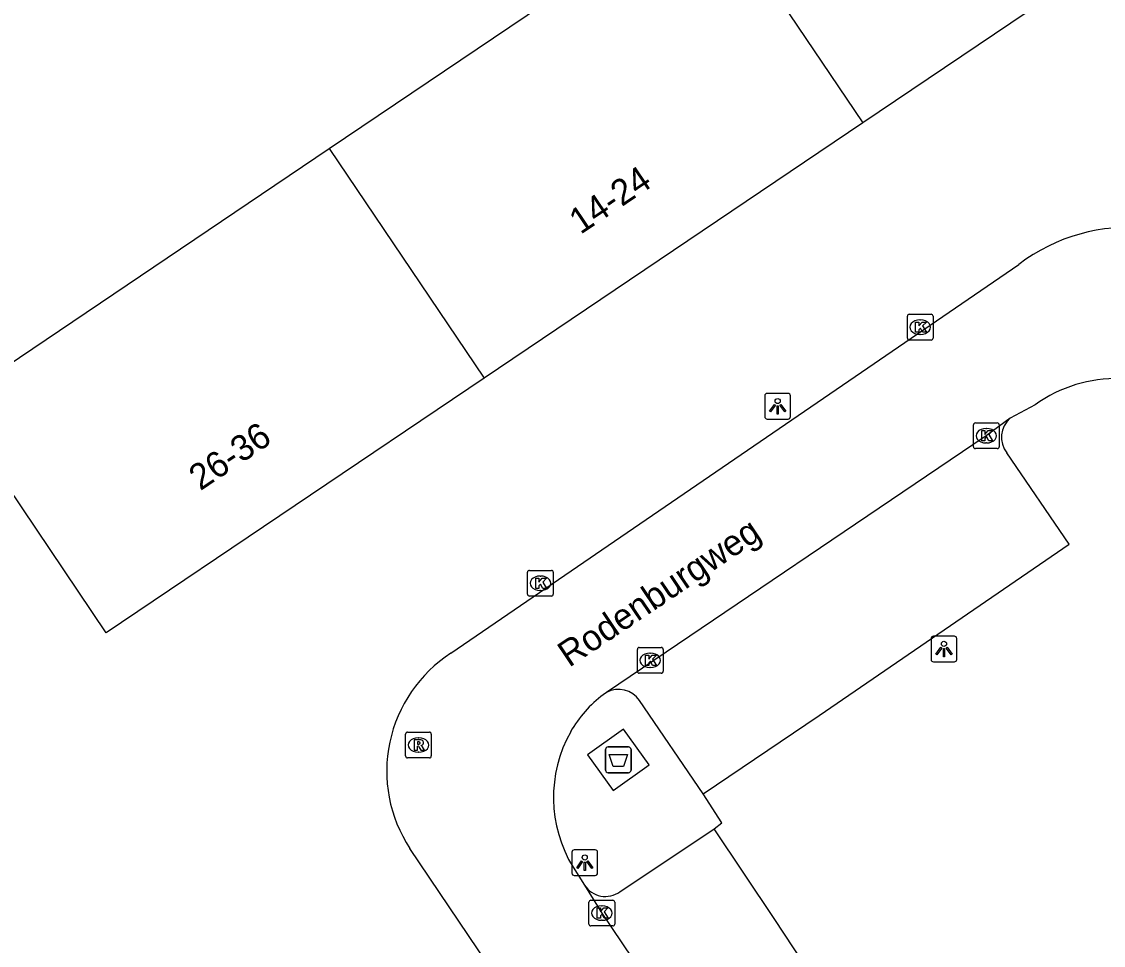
# Model space of a CAD drawing. Extents: x 157466 to 158888, y 383063 to 384677.
# Drawn here: x 158011.77 to 158053.8, y 383756.98 to 383792.86 of the extents above; entities that cross this region are included whole.
import ezdxf

# ---------------------------------------------------------------- set-up
doc = ezdxf.new("R2010")
doc.units = 0
for name, color, linetype in [('IMGEO_Afval_apart_plaats', 7, 'Continuous'), ('IMGEO_Kolk', 7, 'Continuous'), ('IMGEO_Lichtpunt', 7, 'Continuous'), ('IMGEO_Openbare_ruimte_label', 7, 'Continuous'), ('IMGEO_Pand', 7, 'Continuous'), ('IMGEO_Pand_nummerreeks', 7, 'Continuous'), ('IMGEO_Parkeervlak_open', 7, 'Continuous'), ('IMGEO_Rijbaan_lokaal_open', 7, 'Continuous'), ('IMGEO_Rioolput', 7, 'Continuous'), ('IMGEO_Voetpad_gesloten', 7, 'Continuous'), ('IMGEO_Voetpad_open', 7, 'Continuous')]:
    doc.layers.add(name, color=color, linetype=linetype)

msp = doc.modelspace()

# ---------------------------------------------------------------- linework, layer by layer
at = {"layer": 'IMGEO_Afval_apart_plaats'}
for p, q in [((158034.456, 383763.782), (158034.456, 383764.582)), ((158034.456, 383764.582), (158034.456, 383763.782)), ((158034.556, 383764.682), (158035.346, 383764.682)), ((158035.346, 383764.682), (158034.556, 383764.682)), ((158035.446, 383764.582), (158035.446, 383763.782)), ((158035.446, 383763.782), (158035.446, 383764.582)), ((158035.346, 383763.682), (158034.556, 383763.682)), ((158034.556, 383763.682), (158035.346, 383763.682))]:
    msp.add_line(p, q, dxfattribs=at)
msp.add_lwpolyline([(158034.599, 383764.396), (158035.303, 383764.396), (158035.154, 383763.926), (158034.748, 383763.926), (158034.599, 383764.396)], dxfattribs=at)
for centre, start, end in [((158034.556, 383764.582), 90, 180), ((158034.556, 383764.582), 90, 180), ((158035.346, 383764.582), 0, 90), ((158035.346, 383764.582), 360, 90), ((158034.556, 383763.782), 180, 270), ((158034.556, 383763.782), 180, 270), ((158035.346, 383763.782), 270, 0), ((158035.346, 383763.782), 270, 0)]:
    msp.add_arc(centre, 0.1, start, end, dxfattribs=at)
at = {"layer": 'IMGEO_Kolk'}
for p, q in [((158046.182, 383780.564), (158046.182, 383781.416)), ((158046.257, 383781.49), (158047.109, 383781.49)), ((158046.67, 383781.27), (158046.695, 383781.27)), ((158047.183, 383781.416), (158047.183, 383780.564)), ((158047.109, 383780.49), (158046.257, 383780.49)), ((158046.693, 383780.71), (158046.668, 383780.71)), ((158048.748, 383776.347), (158048.748, 383777.199)), ((158048.823, 383777.273), (158049.675, 383777.273)), ((158049.236, 383777.053), (158049.261, 383777.053)), ((158049.749, 383777.199), (158049.749, 383776.347)), ((158049.675, 383776.273), (158048.823, 383776.273)), ((158049.259, 383776.493), (158049.234, 383776.493)), ((158031.499, 383771.542), (158032.351, 383771.542)), ((158031.424, 383770.616), (158031.424, 383771.468)), ((158031.912, 383771.322), (158031.937, 383771.322)), ((158032.425, 383771.468), (158032.425, 383770.616)), ((158031.935, 383770.762), (158031.91, 383770.762)), ((158032.351, 383770.542), (158031.499, 383770.542)), ((158035.694, 383767.622), (158035.694, 383768.474)), ((158035.769, 383768.548), (158036.621, 383768.548)), ((158036.182, 383768.328), (158036.207, 383768.328)), ((158036.695, 383768.474), (158036.695, 383767.622)), ((158036.205, 383767.768), (158036.18, 383767.768)), ((158036.621, 383767.548), (158035.769, 383767.548)), ((158033.812, 383757.804), (158033.812, 383758.656)), ((158033.887, 383758.73), (158034.739, 383758.73)), ((158034.3, 383758.51), (158034.325, 383758.51)), ((158034.813, 383758.656), (158034.813, 383757.804)), ((158034.739, 383757.73), (158033.887, 383757.73)), ((158034.323, 383757.95), (158034.298, 383757.95))]:
    msp.add_line(p, q, dxfattribs=at)
for points in [[(158046.182, 383780.564), (158046.182, 383781.416)], [(158046.257, 383781.49), (158047.109, 383781.49)], [(158046.503, 383781.19), (158046.626, 383781.19), (158046.626, 383781.039), (158046.756, 383781.19), (158046.92, 383781.19), (158046.774, 383781.039), (158046.927, 383780.79), (158046.775, 383780.79), (158046.69, 383780.954), (158046.626, 383780.887), (158046.626, 383780.79), (158046.503, 383780.79), (158046.503, 383781.19)], [(158047.183, 383781.416), (158047.183, 383780.564)], [(158047.109, 383780.49), (158046.257, 383780.49)], [(158048.748, 383776.347), (158048.748, 383777.199)], [(158048.823, 383777.273), (158049.675, 383777.273)], [(158049.069, 383776.973), (158049.192, 383776.973), (158049.192, 383776.822), (158049.322, 383776.973), (158049.486, 383776.973), (158049.34, 383776.822), (158049.493, 383776.573), (158049.341, 383776.573), (158049.256, 383776.737), (158049.192, 383776.67), (158049.192, 383776.573), (158049.069, 383776.573), (158049.069, 383776.973)], [(158049.749, 383777.199), (158049.749, 383776.347)], [(158049.675, 383776.273), (158048.823, 383776.273)], [(158031.499, 383771.542), (158032.351, 383771.542)], [(158031.424, 383770.616), (158031.424, 383771.468)], [(158031.745, 383771.242), (158031.868, 383771.242), (158031.868, 383771.091), (158031.998, 383771.242), (158032.162, 383771.242), (158032.016, 383771.091), (158032.169, 383770.842), (158032.017, 383770.842), (158031.932, 383771.006), (158031.868, 383770.939), (158031.868, 383770.842), (158031.745, 383770.842), (158031.745, 383771.242)], [(158032.425, 383771.468), (158032.425, 383770.616)], [(158032.351, 383770.542), (158031.499, 383770.542)], [(158035.694, 383767.622), (158035.694, 383768.474)], [(158035.769, 383768.548), (158036.621, 383768.548)], [(158036.015, 383768.248), (158036.138, 383768.248), (158036.138, 383768.097), (158036.268, 383768.248), (158036.432, 383768.248), (158036.286, 383768.097), (158036.439, 383767.848), (158036.287, 383767.848), (158036.202, 383768.012), (158036.138, 383767.945), (158036.138, 383767.848), (158036.015, 383767.848), (158036.015, 383768.248)], [(158036.695, 383768.474), (158036.695, 383767.622)], [(158036.621, 383767.548), (158035.769, 383767.548)], [(158033.812, 383757.804), (158033.812, 383758.656)], [(158033.887, 383758.73), (158034.739, 383758.73)], [(158034.813, 383758.656), (158034.813, 383757.804)], [(158034.133, 383758.43), (158034.256, 383758.43), (158034.256, 383758.279), (158034.386, 383758.43), (158034.55, 383758.43), (158034.404, 383758.279), (158034.557, 383758.03), (158034.405, 383758.03), (158034.32, 383758.194), (158034.256, 383758.127), (158034.256, 383758.03), (158034.133, 383758.03), (158034.133, 383758.43)], [(158034.739, 383757.73), (158033.887, 383757.73)]]:
    msp.add_lwpolyline(points, dxfattribs=at)
for centre, start, end in [((158046.259, 383781.414), 91.552, 178.448), ((158046.259, 383781.414), 91.552, 178.448), ((158047.107, 383781.414), 1.552, 88.448), ((158047.107, 383781.414), 1.552, 88.448), ((158046.259, 383780.566), 181.552, 268.448), ((158046.259, 383780.566), 181.552, 268.448), ((158047.107, 383780.566), 271.552, 358.448), ((158047.107, 383780.566), 271.552, 358.448), ((158048.825, 383777.197), 91.552, 178.448), ((158048.825, 383777.197), 91.552, 178.448), ((158049.673, 383777.197), 1.552, 88.448), ((158049.673, 383777.197), 1.552, 88.448), ((158048.825, 383776.349), 181.552, 268.448), ((158048.825, 383776.349), 181.552, 268.448), ((158049.673, 383776.349), 271.552, 358.448), ((158049.673, 383776.349), 271.552, 358.448), ((158031.501, 383771.466), 91.552, 178.448), ((158031.501, 383771.466), 91.552, 178.448), ((158032.349, 383771.466), 1.552, 88.448), ((158032.349, 383771.466), 1.552, 88.448), ((158031.501, 383770.618), 181.552, 268.448), ((158031.501, 383770.618), 181.552, 268.448), ((158032.349, 383770.618), 271.552, 358.448), ((158032.349, 383770.618), 271.552, 358.448), ((158035.771, 383768.472), 91.552, 178.448), ((158035.771, 383768.472), 91.552, 178.448), ((158036.619, 383768.472), 1.552, 88.448), ((158036.619, 383768.472), 1.552, 88.448), ((158035.771, 383767.624), 181.552, 268.448), ((158035.771, 383767.624), 181.552, 268.448), ((158036.619, 383767.624), 271.552, 358.448), ((158036.619, 383767.624), 271.552, 358.448), ((158033.889, 383758.654), 91.552, 178.448), ((158033.889, 383758.654), 91.552, 178.448), ((158034.737, 383758.654), 1.552, 88.448), ((158034.737, 383758.654), 1.552, 88.448), ((158033.889, 383757.806), 181.552, 268.448), ((158033.889, 383757.806), 181.552, 268.448), ((158034.737, 383757.806), 271.552, 358.448), ((158034.737, 383757.806), 271.552, 358.448)]:
    msp.add_arc(centre, 0.0765, start, end, dxfattribs=at)
for centre, major_axis, ratio, start_param, end_param in [((158046.669, 383780.99), (-0.387, 0.002), 0.722429, 4.712389, 7.853982), ((158046.694, 383780.99), (-0.39, 0.002), 0.717154, 1.570796, 4.712389), ((158049.235, 383776.773), (-0.387, 0.002), 0.722429, 4.712389, 7.853982), ((158049.26, 383776.773), (-0.39, 0.002), 0.717154, 1.570796, 4.712389), ((158031.911, 383771.042), (-0.387, 0.002), 0.722429, 4.712389, 7.853982), ((158031.936, 383771.042), (-0.39, 0.002), 0.717154, 1.570796, 4.712389), ((158036.181, 383768.048), (-0.387, 0.002), 0.722429, 4.712389, 7.853982), ((158036.206, 383768.048), (-0.39, 0.002), 0.717154, 1.570796, 4.712389), ((158034.299, 383758.23), (-0.387, 0.002), 0.722429, 4.712389, 7.853982), ((158034.324, 383758.23), (-0.39, 0.002), 0.717154, 1.570796, 4.712389)]:
    msp.add_ellipse(centre, major_axis=major_axis, ratio=ratio, start_param=start_param, end_param=end_param, dxfattribs=at)
at = {"layer": 'IMGEO_Lichtpunt'}
for p, q in [((158040.644, 383778.323), (158040.644, 383777.516)), ((158040.644, 383778.323), (158040.644, 383777.516)), ((158041.546, 383778.418), (158040.738, 383778.418)), ((158041.546, 383778.418), (158040.738, 383778.418)), ((158041.64, 383777.516), (158041.64, 383778.323)), ((158041.64, 383777.516), (158041.64, 383778.323)), ((158040.738, 383777.422), (158041.546, 383777.422)), ((158040.738, 383777.422), (158041.546, 383777.422)), ((158048.007, 383768.986), (158047.199, 383768.986)), ((158048.007, 383768.986), (158047.199, 383768.986)), ((158047.105, 383768.891), (158047.105, 383768.084)), ((158047.105, 383768.891), (158047.105, 383768.084)), ((158048.101, 383768.084), (158048.101, 383768.891)), ((158048.101, 383768.084), (158048.101, 383768.891)), ((158047.199, 383767.99), (158048.007, 383767.99)), ((158047.199, 383767.99), (158048.007, 383767.99)), ((158033.15, 383760.592), (158033.15, 383759.785)), ((158033.15, 383760.592), (158033.15, 383759.785)), ((158034.052, 383760.687), (158033.244, 383760.687)), ((158034.052, 383760.687), (158033.244, 383760.687)), ((158034.146, 383759.785), (158034.146, 383760.592)), ((158034.146, 383759.785), (158034.146, 383760.592)), ((158033.244, 383759.691), (158034.052, 383759.691)), ((158033.244, 383759.691), (158034.052, 383759.691))]:
    msp.add_line(p, q, dxfattribs=at)
for points in [[(158041.018, 383777.987), (158041.057, 383777.959), (158040.869, 383777.697), (158040.831, 383777.724), (158041.018, 383777.987)], [(158041.12, 383777.939), (158041.167, 383777.939), (158041.167, 383777.617), (158041.12, 383777.617), (158041.12, 383777.939)], [(158041.23, 383777.959), (158041.268, 383777.986), (158041.455, 383777.724), (158041.416, 383777.696), (158041.23, 383777.959)], [(158047.479, 383768.555), (158047.518, 383768.527), (158047.33, 383768.265), (158047.292, 383768.292), (158047.479, 383768.555)], [(158047.581, 383768.507), (158047.628, 383768.507), (158047.628, 383768.185), (158047.581, 383768.185), (158047.581, 383768.507)], [(158047.691, 383768.527), (158047.729, 383768.554), (158047.916, 383768.292), (158047.877, 383768.264), (158047.691, 383768.527)], [(158033.524, 383760.256), (158033.563, 383760.228), (158033.375, 383759.966), (158033.337, 383759.993), (158033.524, 383760.256)], [(158033.626, 383760.208), (158033.673, 383760.208), (158033.673, 383759.886), (158033.626, 383759.886), (158033.626, 383760.208)], [(158033.736, 383760.228), (158033.774, 383760.255), (158033.961, 383759.993), (158033.922, 383759.965), (158033.736, 383760.228)]]:
    msp.add_lwpolyline(points, dxfattribs=at)
for centre in [(158041.143, 383778.121), (158047.604, 383768.689), (158033.649, 383760.39)]:
    msp.add_circle(centre, 0.0994, dxfattribs=at)
for centre, start, end in [((158040.738, 383778.323), 90, 180), ((158040.738, 383778.323), 90, 180), ((158041.546, 383778.323), 0, 90), ((158041.546, 383778.323), 0, 90), ((158040.738, 383777.516), 180, 270), ((158040.738, 383777.516), 180, 270), ((158041.546, 383777.516), 270, 0), ((158041.546, 383777.516), 270, 360), ((158047.199, 383768.891), 90, 180), ((158047.199, 383768.891), 90, 180), ((158048.007, 383768.891), 0, 90), ((158048.007, 383768.891), 0, 90), ((158047.199, 383768.084), 180, 270), ((158047.199, 383768.084), 180, 270), ((158048.007, 383768.084), 270, 0), ((158048.007, 383768.084), 270, 360), ((158033.244, 383760.592), 90, 180), ((158033.244, 383760.592), 90, 180), ((158034.052, 383760.592), 0, 90), ((158034.052, 383760.592), 0, 90), ((158033.244, 383759.785), 180, 270), ((158033.244, 383759.785), 180, 270), ((158034.052, 383759.785), 270, 0), ((158034.052, 383759.785), 270, 360)]:
    msp.add_arc(centre, 0.0946, start, end, dxfattribs=at)
at = {"layer": 'IMGEO_Pand'}
for points in [[(158038.433, 383797.849), (158053.11, 383807.743), (158059.126, 383798.819), (158044.449, 383788.925)], [(158023.723, 383787.933), (158038.433, 383797.849)], [(158038.433, 383797.849), (158044.449, 383788.925)], [(158044.449, 383788.925), (158029.739, 383779.009)], [(158029.739, 383779.009), (158015.062, 383769.115), (158009.046, 383778.039), (158023.723, 383787.933)], [(158023.723, 383787.933), (158029.739, 383779.009)]]:
    msp.add_lwpolyline(points, dxfattribs=at)
at = {"layer": 'IMGEO_Parkeervlak_open'}
for points in [[(158038.251, 383762.862), (158042.756, 383765.908), (158052.466, 383772.566), (158050.048, 383776.108)], [(158049.853, 383736.909), (158053.457, 383739.317), (158046.289, 383750), (158041.002, 383758.024), (158038.673, 383761.499)]]:
    msp.add_lwpolyline(points, dxfattribs=at)
msp.add_arc((158050.798, 383776.714), 0.964, 129.914, 218.9684, dxfattribs=at)
at = {"layer": 'IMGEO_Rijbaan_lokaal_open'}
for points in [[(158028.45, 383768.324), (158050.511, 383783.427)], [(158051.141, 383777.976), (158050.179, 383777.454)], [(158050.179, 383777.454), (158049.248, 383776.775), (158034.494, 383766.797)], [(158034.494, 383766.797), (158034.369, 383766.712)], [(158049.287, 383727.567), (158045.967, 383732.532), (158034.09, 383750), (158026.854, 383760.744)], [(158033.196, 383760.009), (158033.641, 383759.315)], [(158033.641, 383759.315), (158034.313, 383758.229), (158039.859, 383750), (158048.318, 383737.448), (158049.577, 383735.566)]]:
    msp.add_lwpolyline(points, dxfattribs=at)
for centre, radius, start, end in [((158054.786, 383777.807), 7.061, 42.0427, 127.2625), ((158054.33, 383773.501), 5.495, 52.3742, 125.4722), ((158031.416, 383763.741), 5.459, 122.9154, 213.3042), ((158037.14, 383762.988), 4.642, 126.6463, 150.4642), ((158037.645, 383762.724), 5.211, 150.6744, 211.3923)]:
    msp.add_arc(centre, radius, start, end, dxfattribs=at)
at = {"layer": 'IMGEO_Rioolput'}
for p, q in [((158026.762, 383765.258), (158027.614, 383765.258)), ((158026.687, 383764.332), (158026.687, 383765.184)), ((158027.175, 383765.038), (158027.2, 383765.038)), ((158027.688, 383765.184), (158027.688, 383764.332)), ((158027.198, 383764.478), (158027.173, 383764.478)), ((158027.614, 383764.258), (158026.762, 383764.258))]:
    msp.add_line(p, q, dxfattribs=at)
for points in [[(158026.762, 383765.258), (158027.614, 383765.258)], [(158026.687, 383764.332), (158026.687, 383765.184)], [(158027.276, 383764.956), (158027.024, 383764.958), (158027.024, 383764.558)], [(158027.202, 383764.877), (158027.148, 383764.877), (158027.148, 383764.796)], [(158027.148, 383764.796), (158027.2, 383764.796)], [(158027.688, 383765.184), (158027.688, 383764.332)], [(158027.024, 383764.558), (158027.148, 383764.558), (158027.148, 383764.72), (158027.159, 383764.72)], [(158027.206, 383764.691), (158027.277, 383764.558), (158027.417, 383764.558), (158027.352, 383764.684)], [(158027.614, 383764.258), (158026.762, 383764.258)]]:
    msp.add_lwpolyline(points, dxfattribs=at)
for centre, radius, start, end in [((158026.764, 383765.182), 0.0765, 91.552, 178.448), ((158026.764, 383765.182), 0.0765, 91.552, 178.448), ((158027.612, 383765.182), 0.0765, 1.552, 88.448), ((158027.612, 383765.182), 0.0765, 1.552, 88.448), ((158027.184, 383764.985), 0.19, 274.7715, 282.9687), ((158027.208, 383764.781), 0.0964, 77.0061, 93.1865), ((158027.222, 383764.838), 0.0378, 276.6634, 79.6772), ((158027.275, 383764.846), 0.109, 350.3612, 89.416), ((158027.273, 383764.846), 0.112, 277.5842, 350.9817), ((158027.158, 383764.667), 0.0533, 26.0293, 88.6989), ((158027.257, 383764.631), 0.108, 29.5134, 73.7905), ((158026.764, 383764.334), 0.0765, 181.552, 268.448), ((158026.764, 383764.334), 0.0765, 181.552, 268.448), ((158027.612, 383764.334), 0.0765, 271.552, 358.448), ((158027.612, 383764.334), 0.0765, 271.552, 358.448)]:
    msp.add_arc(centre, radius, start, end, dxfattribs=at)
for centre, major_axis, ratio, start_param, end_param in [((158027.174, 383764.758), (-0.387, 0.002), 0.722429, 4.712389, 7.853982), ((158027.199, 383764.758), (-0.39, 0.002), 0.717154, 1.570796, 4.712389)]:
    msp.add_ellipse(centre, major_axis=major_axis, ratio=ratio, start_param=start_param, end_param=end_param, dxfattribs=at)
at = {"layer": 'IMGEO_Voetpad_gesloten'}
msp.add_lwpolyline([(158034.751, 383762.989), (158036.145, 383763.99), (158035.151, 383765.374), (158033.757, 383764.373), (158034.751, 383762.989)], dxfattribs=at)
at = {"layer": 'IMGEO_Voetpad_open'}
for points in [[(158038.251, 383762.862), (158035.771, 383766.482)], [(158038.673, 383761.499), (158038.979, 383761.731), (158038.251, 383762.862)], [(158035.013, 383759.061), (158038.673, 383761.499)]]:
    msp.add_lwpolyline(points, dxfattribs=at)
for centre, radius, start, end in [((158034.965, 383765.962), 0.959, 32.8359, 119.4508), ((158034.446, 383759.832), 0.957, 212.6912, 306.3318)]:
    msp.add_arc(centre, radius, start, end, dxfattribs=at)

# ---------------------------------------------------------------- texts
at = {"layer": 'IMGEO_Openbare_ruimte_label'}
msp.add_text('Rodenburgweg', height=1, rotation=33.9125, dxfattribs=at).set_placement((158033.042, 383767.754))
at = {"layer": 'IMGEO_Pand_nummerreeks'}
for s, p in [('14-24', (158033.484, 383784.573)), ('26-36', (158018.715, 383774.617))]:
    msp.add_text(s, height=1, rotation=33.9843, dxfattribs=at).set_placement(p)

doc.saveas('drawing.dxf')
